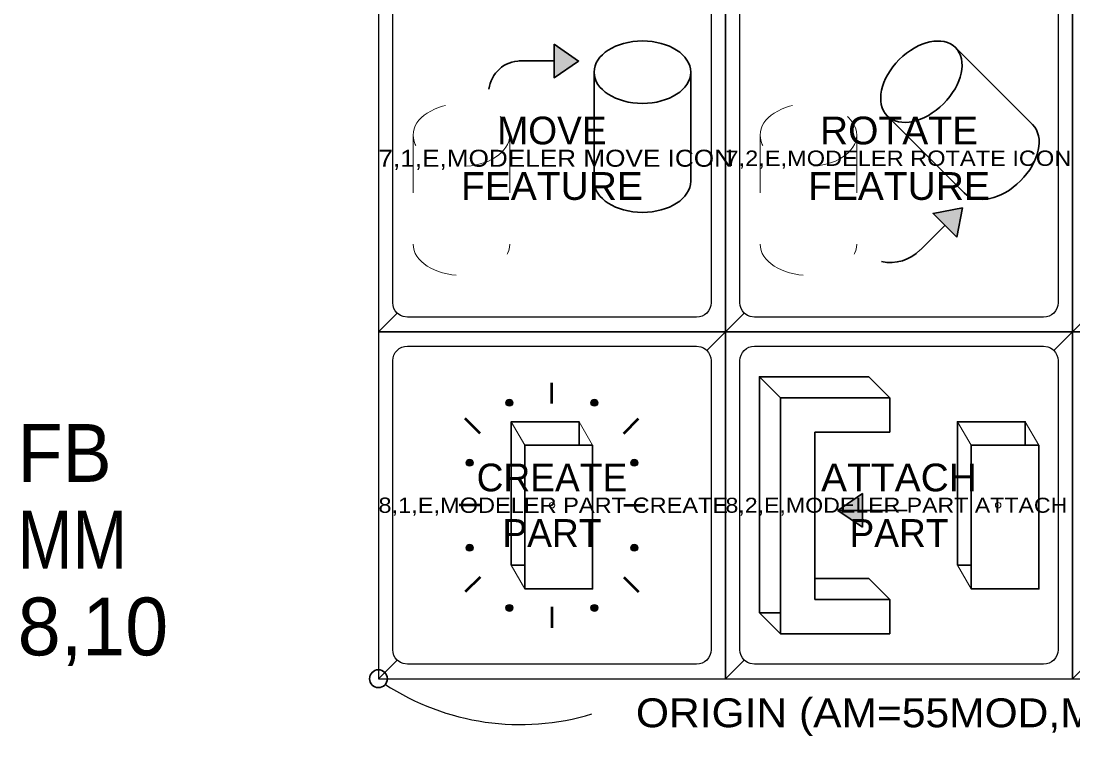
# Model space of a CAD drawing. Extents: x 95909.2 to 95923.3, y 90965 to 90971.2.
# Drawn here: x 95909.169 to 95910.988, y 90966.261 to 90967.498 of the extents above; entities that cross this region are included whole.
import ezdxf
from ezdxf.enums import TextEntityAlignment as Align

# ---------------------------------------------------------------- set-up
doc = ezdxf.new("R2010")
doc.units = 0
doc.header["$LTSCALE"] = 0.019
doc.header["$PDMODE"] = 32
doc.header["$PDSIZE"] = 0.0095
doc.linetypes.add('MEDIUM_DASHED', pattern=[4.5, 3, -1.5])
for name, color, linetype, lineweight in [('1', 7, 'Continuous', 25), ('10', 7, 'Continuous', 13), ('2', 7, 'Continuous', 25), ('3', 7, 'Continuous', 25), ('4', 7, 'Continuous', 25), ('6', 7, 'Continuous', 13), ('7', 7, 'Continuous', 35)]:
    doc.layers.add(name, color=color, linetype=linetype, lineweight=lineweight)
doc.layers.add('5', color=7, linetype='Continuous')
doc.layers.add('63', color=7, linetype='Continuous')

msp = doc.modelspace()

# ---------------------------------------------------------------- hatches: boundary and pattern name
at = {"layer": '6'}
for points in [[(95910.0905, 90967.4577), (95910.1328, 90967.4284), (95910.0904, 90967.3995)], [(95910.787, 90967.124), (95910.7963, 90967.1745), (95910.7457, 90967.165)], [(95910.01328, 90966.84362, 1), (95910.01328, 90966.83162, 1)], [(95910.16448, 90966.84186, 1), (95910.15599, 90966.83337, 1)], [(95909.93838, 90966.73371, 1), (95909.95038, 90966.73371, 1)], [(95910.23514, 90966.73371, 1), (95910.22314, 90966.73371, 1)], [(95910.6236, 90966.6222), (95910.5813, 90966.6513), (95910.6236, 90966.6804)], [(95909.93838, 90966.58676, 1), (95909.95038, 90966.58676, 1)], [(95910.23514, 90966.58676, 1), (95910.22314, 90966.58676, 1)], [(95910.00904, 90966.4786, 1), (95910.01753, 90966.48709, 1)], [(95910.16024, 90966.47685, 1), (95910.16024, 90966.48885, 1)]]:
    msp.add_hatch(color=256, dxfattribs=at).paths.add_polyline_path(points)

# ---------------------------------------------------------------- linework, layer by layer
at = {"layer": '1'}
for points in [[(95909.7868, 90966.9603), (95910.3868, 90966.9603), (95910.3868, 90967.5603), (95909.7868, 90967.5603)], [(95910.3868, 90966.9603), (95910.9868, 90966.9603), (95910.9868, 90967.5603), (95910.3868, 90967.5603)], [(95910.9868, 90966.9603), (95911.5868, 90966.9603), (95911.5868, 90967.5603), (95910.9868, 90967.5603)], [(95909.7868, 90966.3603), (95910.3868, 90966.3603), (95910.3868, 90966.9603), (95909.7868, 90966.9603)], [(95910.3868, 90966.3603), (95910.9868, 90966.3603), (95910.9868, 90966.9603), (95910.3868, 90966.9603)], [(95910.9868, 90966.3603), (95911.5868, 90966.3603), (95911.5868, 90966.9603), (95910.9868, 90966.9603)]]:
    msp.add_lwpolyline(points, close=True, dxfattribs=at)
at = {"layer": '10'}
msp.add_lwpolyline([(95909.7868, 90971.1603), (95915.7868, 90971.1603), (95915.7868, 90966.3603), (95909.7868, 90966.3603)], close=True, dxfattribs=at)
at = {"layer": '2'}
for points in [[(95909.7868, 90966.9603), (95910.3868, 90966.9603), (95910.3868, 90967.5603), (95909.7868, 90967.5603)], [(95910.3868, 90966.9603), (95910.9868, 90966.9603), (95910.9868, 90967.5603), (95910.3868, 90967.5603)], [(95910.9868, 90966.9603), (95911.5868, 90966.9603), (95911.5868, 90967.5603), (95910.9868, 90967.5603)], [(95909.7868, 90966.3603), (95910.3868, 90966.3603), (95910.3868, 90966.9603), (95909.7868, 90966.9603)], [(95910.3868, 90966.3603), (95910.9868, 90966.3603), (95910.9868, 90966.9603), (95910.3868, 90966.9603)], [(95910.9868, 90966.3603), (95911.5868, 90966.3603), (95911.5868, 90966.9603), (95910.9868, 90966.9603)]]:
    msp.add_lwpolyline(points, close=True, dxfattribs=at)
at = {"layer": '3'}
for points in [[(95910.3868, 90967.5603), (95909.7868, 90967.5603), (95909.7868, 90966.9603), (95909.8191, 90966.9926), (95909.816, 90966.9964), (95909.8137, 90967.0007), (95909.8123, 90967.0054), (95909.8118, 90967.0103), (95909.8118, 90967.5103), (95909.8123, 90967.5152), (95909.8137, 90967.5199), (95909.816, 90967.5242), (95909.8191, 90967.528), (95909.8191, 90967.528), (95909.8229, 90967.5311), (95909.8272, 90967.5334), (95909.8319, 90967.5348), (95909.8368, 90967.5353), (95910.3368, 90967.5353), (95910.3441, 90967.5342), (95910.3486, 90967.5323), (95910.3527, 90967.5296), (95910.3545, 90967.528)], [(95910.9868, 90967.5603), (95910.3868, 90967.5603), (95910.3868, 90966.9603), (95910.4191, 90966.9926), (95910.416, 90966.9964), (95910.4137, 90967.0007), (95910.4123, 90967.0054), (95910.4118, 90967.0103), (95910.4118, 90967.5103), (95910.4123, 90967.5152), (95910.4137, 90967.5199), (95910.416, 90967.5242), (95910.4191, 90967.528), (95910.4191, 90967.528), (95910.4229, 90967.5311), (95910.4272, 90967.5334), (95910.4319, 90967.5348), (95910.4368, 90967.5353), (95910.9368, 90967.5353), (95910.9441, 90967.5342), (95910.9486, 90967.5323), (95910.9527, 90967.5296), (95910.9545, 90967.528)], [(95911.5868, 90967.5603), (95910.9868, 90967.5603), (95910.9868, 90966.9603), (95911.0191, 90966.9926), (95911.016, 90966.9964), (95911.0137, 90967.0007), (95911.0123, 90967.0054), (95911.0118, 90967.0103), (95911.0118, 90967.5103), (95911.0123, 90967.5152), (95911.0137, 90967.5199), (95911.016, 90967.5242), (95911.0191, 90967.528), (95911.0191, 90967.528), (95911.0229, 90967.5311), (95911.0272, 90967.5334), (95911.0319, 90967.5348), (95911.0368, 90967.5353), (95911.5368, 90967.5353), (95911.5441, 90967.5342), (95911.5486, 90967.5323), (95911.5527, 90967.5296), (95911.5545, 90967.528)], [(95910.3868, 90966.9603), (95909.7868, 90966.9603), (95909.7868, 90966.3603), (95909.8191, 90966.3926), (95909.816, 90966.3964), (95909.8137, 90966.4007), (95909.8123, 90966.4054), (95909.8118, 90966.4103), (95909.8118, 90966.9103), (95909.8123, 90966.9152), (95909.8137, 90966.9199), (95909.816, 90966.9242), (95909.8191, 90966.928), (95909.8191, 90966.928), (95909.8229, 90966.9311), (95909.8272, 90966.9334), (95909.8319, 90966.9348), (95909.8368, 90966.9353), (95910.3368, 90966.9353), (95910.3441, 90966.9342), (95910.3486, 90966.9323), (95910.3527, 90966.9296), (95910.3545, 90966.928)], [(95910.9868, 90966.9603), (95910.3868, 90966.9603), (95910.3868, 90966.3603), (95910.4191, 90966.3926), (95910.416, 90966.3964), (95910.4137, 90966.4007), (95910.4123, 90966.4054), (95910.4118, 90966.4103), (95910.4118, 90966.9103), (95910.4123, 90966.9152), (95910.4137, 90966.9199), (95910.416, 90966.9242), (95910.4191, 90966.928), (95910.4191, 90966.928), (95910.4229, 90966.9311), (95910.4272, 90966.9334), (95910.4319, 90966.9348), (95910.4368, 90966.9353), (95910.9368, 90966.9353), (95910.9441, 90966.9342), (95910.9486, 90966.9323), (95910.9527, 90966.9296), (95910.9545, 90966.928)], [(95911.5868, 90966.9603), (95910.9868, 90966.9603), (95910.9868, 90966.3603), (95911.0191, 90966.3926), (95911.016, 90966.3964), (95911.0137, 90966.4007), (95911.0123, 90966.4054), (95911.0118, 90966.4103), (95911.0118, 90966.9103), (95911.0123, 90966.9152), (95911.0137, 90966.9199), (95911.016, 90966.9242), (95911.0191, 90966.928), (95911.0191, 90966.928), (95911.0229, 90966.9311), (95911.0272, 90966.9334), (95911.0319, 90966.9348), (95911.0368, 90966.9353), (95911.5368, 90966.9353), (95911.5441, 90966.9342), (95911.5486, 90966.9323), (95911.5527, 90966.9296), (95911.5545, 90966.928)]]:
    msp.add_lwpolyline(points, close=True, dxfattribs=at)
at = {"layer": '4'}
for points in [[(95909.7868, 90966.9603), (95910.3868, 90966.9603), (95910.3868, 90967.5603), (95910.3545, 90967.528), (95910.3576, 90967.5242), (95910.3599, 90967.5199), (95910.3613, 90967.5152), (95910.3618, 90967.5103), (95910.3618, 90967.0103), (95910.3613, 90967.0054), (95910.3599, 90967.0007), (95910.3576, 90966.9964), (95910.3545, 90966.9926), (95910.3545, 90966.9926), (95910.3507, 90966.9895), (95910.3464, 90966.9872), (95910.3417, 90966.9858), (95910.3368, 90966.9853), (95909.8368, 90966.9853), (95909.8295, 90966.9864), (95909.825, 90966.9883), (95909.8209, 90966.991), (95909.8191, 90966.9926)], [(95910.3868, 90966.9603), (95910.9868, 90966.9603), (95910.9868, 90967.5603), (95910.9545, 90967.528), (95910.9576, 90967.5242), (95910.9599, 90967.5199), (95910.9613, 90967.5152), (95910.9618, 90967.5103), (95910.9618, 90967.0103), (95910.9613, 90967.0054), (95910.9599, 90967.0007), (95910.9576, 90966.9964), (95910.9545, 90966.9926), (95910.9545, 90966.9926), (95910.9507, 90966.9895), (95910.9464, 90966.9872), (95910.9417, 90966.9858), (95910.9368, 90966.9853), (95910.4368, 90966.9853), (95910.4295, 90966.9864), (95910.425, 90966.9883), (95910.4209, 90966.991), (95910.4191, 90966.9926)], [(95910.9868, 90966.9603), (95911.5868, 90966.9603), (95911.5868, 90967.5603), (95911.5545, 90967.528), (95911.5576, 90967.5242), (95911.5599, 90967.5199), (95911.5613, 90967.5152), (95911.5618, 90967.5103), (95911.5618, 90967.0103), (95911.5613, 90967.0054), (95911.5599, 90967.0007), (95911.5576, 90966.9964), (95911.5545, 90966.9926), (95911.5545, 90966.9926), (95911.5507, 90966.9895), (95911.5464, 90966.9872), (95911.5417, 90966.9858), (95911.5368, 90966.9853), (95911.0368, 90966.9853), (95911.0295, 90966.9864), (95911.025, 90966.9883), (95911.0209, 90966.991), (95911.0191, 90966.9926)], [(95909.7868, 90966.3603), (95910.3868, 90966.3603), (95910.3868, 90966.9603), (95910.3545, 90966.928), (95910.3576, 90966.9242), (95910.3599, 90966.9199), (95910.3613, 90966.9152), (95910.3618, 90966.9103), (95910.3618, 90966.4103), (95910.3613, 90966.4054), (95910.3599, 90966.4007), (95910.3576, 90966.3964), (95910.3545, 90966.3926), (95910.3545, 90966.3926), (95910.3507, 90966.3895), (95910.3464, 90966.3872), (95910.3417, 90966.3858), (95910.3368, 90966.3853), (95909.8368, 90966.3853), (95909.8295, 90966.3864), (95909.825, 90966.3883), (95909.8209, 90966.391), (95909.8191, 90966.3926)], [(95910.3868, 90966.3603), (95910.9868, 90966.3603), (95910.9868, 90966.9603), (95910.9545, 90966.928), (95910.9576, 90966.9242), (95910.9599, 90966.9199), (95910.9613, 90966.9152), (95910.9618, 90966.9103), (95910.9618, 90966.4103), (95910.9613, 90966.4054), (95910.9599, 90966.4007), (95910.9576, 90966.3964), (95910.9545, 90966.3926), (95910.9545, 90966.3926), (95910.9507, 90966.3895), (95910.9464, 90966.3872), (95910.9417, 90966.3858), (95910.9368, 90966.3853), (95910.4368, 90966.3853), (95910.4295, 90966.3864), (95910.425, 90966.3883), (95910.4209, 90966.391), (95910.4191, 90966.3926)], [(95910.9868, 90966.3603), (95911.5868, 90966.3603), (95911.5868, 90966.9603), (95911.5545, 90966.928), (95911.5576, 90966.9242), (95911.5599, 90966.9199), (95911.5613, 90966.9152), (95911.5618, 90966.9103), (95911.5618, 90966.4103), (95911.5613, 90966.4054), (95911.5599, 90966.4007), (95911.5576, 90966.3964), (95911.5545, 90966.3926), (95911.5545, 90966.3926), (95911.5507, 90966.3895), (95911.5464, 90966.3872), (95911.5417, 90966.3858), (95911.5368, 90966.3853), (95911.0368, 90966.3853), (95911.0295, 90966.3864), (95911.025, 90966.3883), (95911.0209, 90966.391), (95911.0191, 90966.3926)]]:
    msp.add_lwpolyline(points, close=True, dxfattribs=at)
at = {"layer": '6', "lineweight": 35}
for p, q in [((95910.7845, 90967.4517), (95910.9178, 90967.3185)), ((95910.0904, 90967.4285), (95910.0301, 90967.4285)), ((95910.1597, 90967.4091), (95910.1597, 90967.2207)), ((95910.3268, 90967.4091), (95910.3268, 90967.2207)), ((95910.6664, 90967.3336), (95910.7996, 90967.2003)), ((95910.7664, 90967.1445), (95910.7237, 90967.1018)), ((95910.6707, 90966.846), (95910.6707, 90966.7866)), ((95910.7007, 90966.6513), (95910.5813, 90966.6513)), ((95910.0164, 90966.5566), (95910.0399, 90966.5566)), ((95910.7879, 90966.5566), (95910.8114, 90966.5566)), ((95910.5414, 90966.5339), (95910.6345, 90966.5339)), ((95910.6707, 90966.438), (95910.6707, 90966.4976))]:
    msp.add_line(p, q, dxfattribs=at)
at = {"layer": '6', "linetype": 'MEDIUM_DASHED'}
for p, q in [((95909.8468, 90967.3003), (95909.8468, 90967.1119)), ((95910.0139, 90967.3003), (95910.0139, 90967.1119)), ((95910.4468, 90967.3003), (95910.4468, 90967.1119)), ((95910.6139, 90967.3003), (95910.6139, 90967.1119))]:
    msp.add_line(p, q, dxfattribs=at)
at = {"layer": '6'}
for p, q in [((95910.4819, 90966.846), (95910.4456, 90966.8824)), ((95910.6707, 90966.846), (95910.6345, 90966.8824)), ((95910.0399, 90966.764), (95910.0164, 90966.8048)), ((95910.1571, 90966.764), (95910.1336, 90966.8048)), ((95910.8114, 90966.764), (95910.7879, 90966.8048)), ((95910.9286, 90966.764), (95910.9051, 90966.8048)), ((95910.0399, 90966.5157), (95910.0164, 90966.5566)), ((95910.8114, 90966.5157), (95910.7879, 90966.5566)), ((95910.6707, 90966.4976), (95910.6345, 90966.5339)), ((95910.4819, 90966.438), (95910.4456, 90966.4744))]:
    msp.add_line(p, q, dxfattribs=at)
at = {"layer": '6', "lineweight": 53}
for p, q in [((95910.0868, 90966.8361), (95910.0868, 90966.8721)), ((95909.9624, 90966.7846), (95909.9369, 90966.81)), ((95910.2111, 90966.7846), (95910.2366, 90966.81)), ((95909.9624, 90966.6603), (95909.9264, 90966.6603)), ((95910.2111, 90966.6603), (95910.2471, 90966.6603)), ((95909.9624, 90966.5358), (95909.9369, 90966.5104)), ((95910.2111, 90966.5358), (95910.2366, 90966.5104)), ((95910.0868, 90966.4844), (95910.0868, 90966.4484))]:
    msp.add_line(p, q, dxfattribs=at)
at = {"layer": '6', "lineweight": 35}
for points in [[(95910.0905, 90967.4577), (95910.1328, 90967.4284), (95910.0904, 90967.3995)], [(95910.787, 90967.124), (95910.7963, 90967.1745), (95910.7457, 90967.165)], [(95910.0399, 90966.5157), (95910.1571, 90966.5157), (95910.1571, 90966.764), (95910.0399, 90966.764)], [(95910.8114, 90966.5157), (95910.9286, 90966.5157), (95910.9286, 90966.764), (95910.8114, 90966.764)], [(95910.6236, 90966.6222), (95910.5813, 90966.6513), (95910.6236, 90966.6804)]]:
    msp.add_lwpolyline(points, close=True, dxfattribs=at)
for points in [[(95910.6345, 90966.8824), (95910.4456, 90966.8824), (95910.4456, 90966.4744), (95910.4819, 90966.4744)], [(95910.6707, 90966.846), (95910.4819, 90966.846), (95910.4819, 90966.438), (95910.6707, 90966.438)], [(95910.1336, 90966.764), (95910.1336, 90966.8048), (95910.0164, 90966.8048), (95910.0164, 90966.5566)], [(95910.9051, 90966.764), (95910.9051, 90966.8048), (95910.7879, 90966.8048), (95910.7879, 90966.5566)], [(95910.6707, 90966.7866), (95910.5414, 90966.7866), (95910.5414, 90966.4976), (95910.6707, 90966.4976)]]:
    msp.add_lwpolyline(points, dxfattribs=at)
at = {"layer": '6', "lineweight": 25}
for centre in [(95910.01328, 90966.83762), (95910.16023, 90966.83762), (95909.94438, 90966.73371), (95910.22914, 90966.73371), (95909.94438, 90966.58676), (95910.22914, 90966.58676), (95910.01329, 90966.48285), (95910.16024, 90966.48285)]:
    msp.add_circle(centre, 0.006, dxfattribs=at)
at = {"layer": '6', "lineweight": 35}
for centre, radius, start, end in [((95910.03274, 90967.37326), 0.05528, 89.99932, 173.51283), ((95910.67111, 90967.15432), 0.0743, 258.59859, 315.00805)]:
    msp.add_arc(centre, radius, start, end, dxfattribs=at)
for centre, major_axis in [((95910.24323, 90967.40911), (0.08353, 0)), ((95910.72547, 90967.39266), (0.05907, 0.05907))]:
    msp.add_ellipse(centre, major_axis=major_axis, ratio=0.64664, dxfattribs=at)
at = {"layer": '6', "linetype": 'MEDIUM_DASHED'}
for centre in [(95909.93028, 90967.3003), (95910.53028, 90967.3003)]:
    msp.add_ellipse(centre, major_axis=(0.08353, 0), ratio=0.64664, dxfattribs=at)
at = {"layer": '6', "lineweight": 35}
for centre, major_axis in [((95910.85872, 90967.25941), (0.05907, 0.05907)), ((95910.24323, 90967.22066), (0.08353, 0))]:
    msp.add_ellipse(centre, major_axis=major_axis, ratio=0.64664, start_param=3.1416618, end_param=6.2831028, dxfattribs=at)
at = {"layer": '6', "linetype": 'MEDIUM_DASHED'}
for centre in [(95909.93028, 90967.11185), (95910.53028, 90967.11185)]:
    msp.add_ellipse(centre, major_axis=(0.08353, 0), ratio=0.64664, start_param=3.1416618, end_param=6.2831028, dxfattribs=at)
at = {"layer": '6'}
for p in [(95910.0868, 90966.6603), (95910.8582, 90966.6603)]:
    msp.add_point(p, dxfattribs=at)
at = {"layer": '7'}
msp.add_circle((95909.7868, 90966.3603), 0.01543, dxfattribs=at)
at = {"layer": '7', "lineweight": 25}
msp.add_arc((95910.03203, 90966.70755), 0.42644, 236.68307, 286.88652, dxfattribs=at)

# ---------------------------------------------------------------- texts
at = {"layer": '5'}
for s, p in [('MOVE', (95910.0868, 90967.2843)), ('CREATE', (95910.08675, 90966.6843)), ('PART', (95910.0868, 90966.5883)), ('PART', (95910.6868, 90966.5883))]:
    msp.add_text(s, height=0.048, dxfattribs=at).set_placement(p, align=Align.CENTER)
at = {"layer": '5', "width": 1.05}
for s, p in [('ROTATE', (95910.68685, 90967.2843)), ('FEATURE', (95910.0868, 90967.1883)), ('FEATURE', (95910.6868, 90967.1883)), ('ATTACH', (95910.6868, 90966.6843))]:
    msp.add_text(s, height=0.048, dxfattribs=at).set_placement(p, align=Align.CENTER)
at = {"layer": '63'}
for s, height, width, p in [('7,1,E,MODELER MOVE ICON', 0.0294, 1.15, (95909.7868, 90967.2456)), ('7,2,E,MODELER ROTATE ICON', 0.0265, 1.15, (95910.3868, 90967.2471)), ('FB', 0.1, 0.95, (95909.1631, 90966.7007)), ('8,1,E,MODELER PART CREATE', 0.0265, 1.15, (95909.7868, 90966.6471)), ('8,2,E,MODELER PART ATTACH', 0.026, 1.15, (95910.3868, 90966.6473)), ('MM', 0.1, 0.85, (95909.1631, 90966.5507))]:
    msp.add_text(s, height=height, dxfattribs=dict(at, width=width)).set_placement(p)
msp.add_text('8,10', height=0.1, dxfattribs=at).set_placement((95909.1631, 90966.4007))
at = {"layer": '7', "width": 1.1}
msp.add_text('ORIGIN (AM=55MOD,M1)', height=0.05, dxfattribs=at).set_placement((95910.66205, 90966.2764), align=Align.CENTER)

doc.saveas('drawing.dxf')
